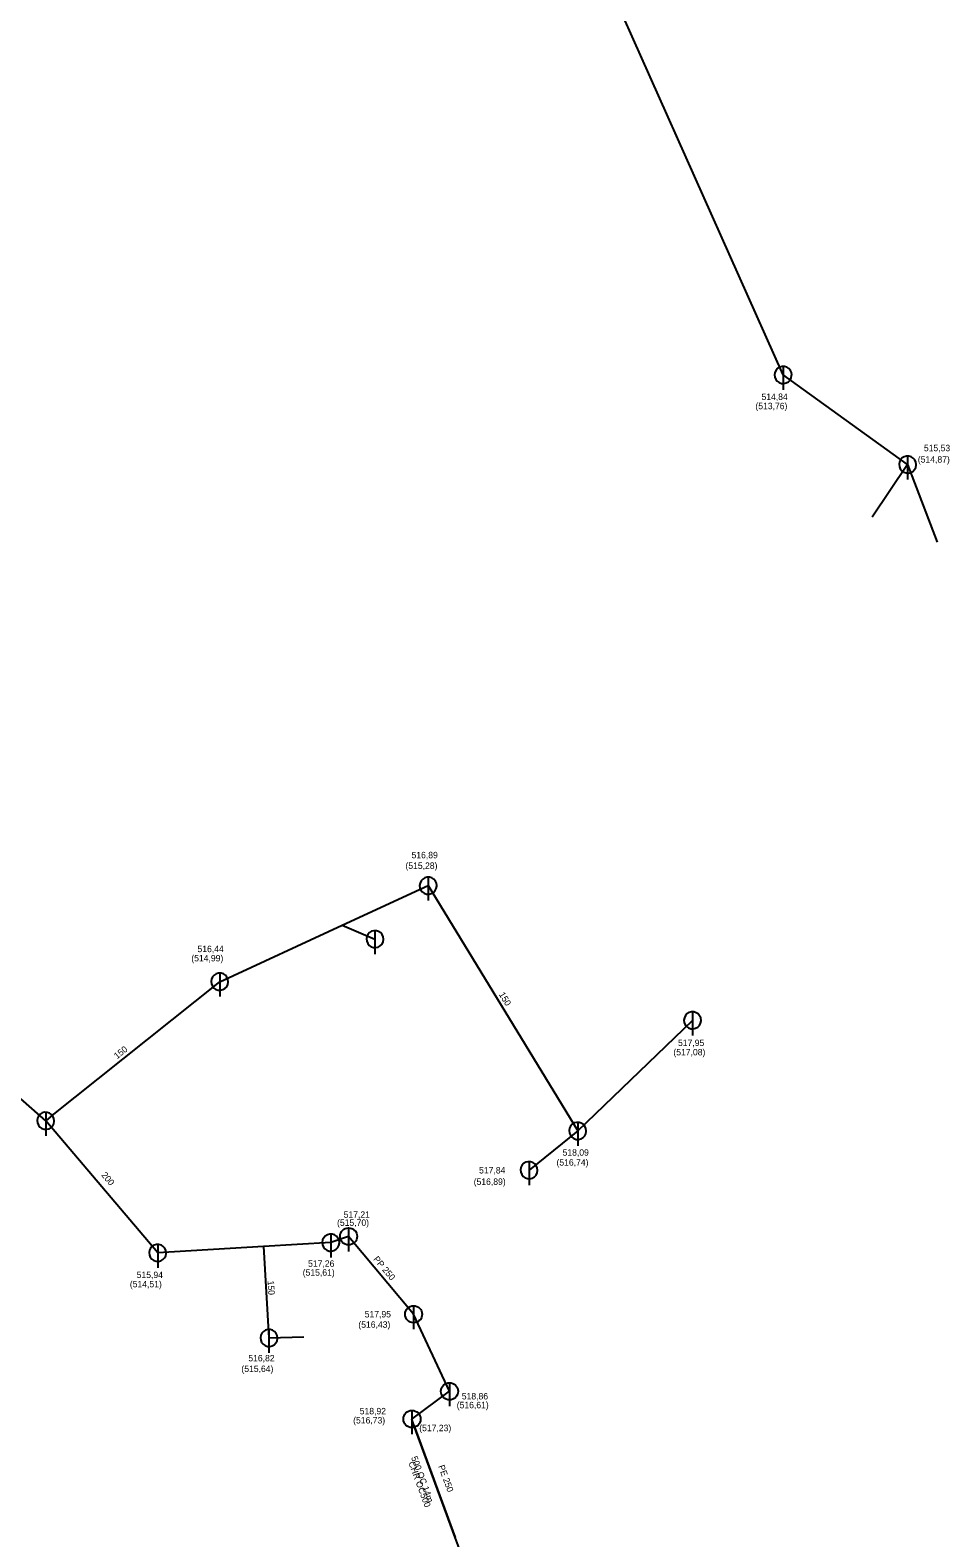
# Model space of a CAD drawing. Extents: x -476058 to -471893, y -1155786 to -1152000.
# Drawn here: x -474946.6 to -474839.2, y -1154439.5 to -1154263.3 of the extents above; entities that cross this region are included whole.
import ezdxf

# ---------------------------------------------------------------- set-up
doc = ezdxf.new("R2010")
doc.units = 0
for name, color, linetype in [('Vrstva 10', 7, 'Continuous'), ('Vrstva 17', 7, 'Continuous'), ('Vrstva 18', 7, 'Continuous'), ('Vrstva 19', 7, 'Continuous'), ('Vrstva 20', 7, 'Continuous'), ('Vrstva 23', 7, 'Continuous'), ('Vrstva 3', 7, 'Continuous'), ('Vrstva 4', 7, 'Continuous'), ('Vrstva 40', 7, 'Continuous'), ('Vrstva 45', 7, 'Continuous'), ('Vrstva 50', 7, 'Continuous'), ('Vrstva 51', 7, 'Continuous')]:
    doc.layers.add(name, color=color, linetype=linetype)

msp = doc.modelspace()

# ---------------------------------------------------------------- linework, layer by layer
at = {"layer": 'Vrstva 10'}
for p, q in [((-474858.62, -1154302.63), (-474858.62, -1154305.38)), ((-474844.08, -1154313.1), (-474844.08, -1154315.85)), ((-474900.08, -1154362.3), (-474900.08, -1154365.05)), ((-474906.29, -1154368.55), (-474906.29, -1154371.3)), ((-474924.42, -1154373.52), (-474924.42, -1154376.27)), ((-474869.21, -1154378.04), (-474869.21, -1154380.79)), ((-474944.74, -1154389.78), (-474944.74, -1154392.52)), ((-474882.61, -1154390.95), (-474882.61, -1154393.7)), ((-474888.29, -1154395.54), (-474888.29, -1154398.29)), ((-474911.45, -1154404.01), (-474911.45, -1154406.75)), ((-474909.37, -1154403.28), (-474909.37, -1154406.03)), ((-474931.67, -1154405.2), (-474931.67, -1154407.95)), ((-474901.78, -1154412.38), (-474901.78, -1154415.13)), ((-474918.67, -1154415.15), (-474918.67, -1154417.9)), ((-474897.59, -1154421.38), (-474897.59, -1154424.13)), ((-474901.97, -1154424.62), (-474901.97, -1154427.37))]:
    msp.add_line(p, q, dxfattribs=at)
for points in [[(-474857.62, -1154303.63), (-474857.66, -1154303.35), (-474857.78, -1154303.1), (-474857.96, -1154302.88), (-474858.2, -1154302.73), (-474858.47, -1154302.65), (-474858.75, -1154302.64), (-474859.02, -1154302.72), (-474859.26, -1154302.86), (-474859.45, -1154303.07), (-474859.58, -1154303.33), (-474859.62, -1154303.61), (-474859.59, -1154303.89), (-474859.48, -1154304.15), (-474859.31, -1154304.37), (-474859.08, -1154304.53), (-474858.81, -1154304.62), (-474858.53, -1154304.63), (-474858.25, -1154304.56), (-474858.01, -1154304.42), (-474857.81, -1154304.22), (-474857.68, -1154303.97), (-474857.63, -1154303.69), (-474857.62, -1154303.63)], [(-474843.08, -1154314.1), (-474843.12, -1154313.82), (-474843.24, -1154313.56), (-474843.42, -1154313.35), (-474843.66, -1154313.19), (-474843.93, -1154313.11), (-474844.21, -1154313.11), (-474844.48, -1154313.18), (-474844.72, -1154313.33), (-474844.91, -1154313.54), (-474845.03, -1154313.79), (-474845.08, -1154314.07), (-474845.05, -1154314.35), (-474844.94, -1154314.61), (-474844.76, -1154314.83), (-474844.53, -1154314.99), (-474844.26, -1154315.08), (-474843.98, -1154315.09), (-474843.71, -1154315.03), (-474843.46, -1154314.89), (-474843.27, -1154314.68), (-474843.14, -1154314.43), (-474843.08, -1154314.16), (-474843.08, -1154314.1)], [(-474899.08, -1154363.3), (-474899.12, -1154363.02), (-474899.24, -1154362.76), (-474899.42, -1154362.55), (-474899.66, -1154362.4), (-474899.93, -1154362.31), (-474900.21, -1154362.31), (-474900.48, -1154362.38), (-474900.72, -1154362.53), (-474900.91, -1154362.74), (-474901.03, -1154362.99), (-474901.08, -1154363.27), (-474901.05, -1154363.55), (-474900.94, -1154363.81), (-474900.76, -1154364.03), (-474900.53, -1154364.19), (-474900.26, -1154364.28), (-474899.98, -1154364.3), (-474899.71, -1154364.23), (-474899.46, -1154364.09), (-474899.27, -1154363.88), (-474899.14, -1154363.63), (-474899.08, -1154363.36), (-474899.08, -1154363.3)], [(-474905.29, -1154369.55), (-474905.32, -1154369.27), (-474905.44, -1154369.01), (-474905.62, -1154368.8), (-474905.86, -1154368.64), (-474906.13, -1154368.56), (-474906.41, -1154368.56), (-474906.68, -1154368.63), (-474906.92, -1154368.78), (-474907.11, -1154368.99), (-474907.24, -1154369.24), (-474907.29, -1154369.52), (-474907.25, -1154369.8), (-474907.14, -1154370.06), (-474906.97, -1154370.28), (-474906.73, -1154370.44), (-474906.47, -1154370.53), (-474906.18, -1154370.54), (-474905.91, -1154370.48), (-474905.67, -1154370.34), (-474905.47, -1154370.13), (-474905.34, -1154369.88), (-474905.29, -1154369.6), (-474905.29, -1154369.55)], [(-474923.42, -1154374.52), (-474923.46, -1154374.25), (-474923.58, -1154373.99), (-474923.76, -1154373.77), (-474924, -1154373.62), (-474924.27, -1154373.54), (-474924.55, -1154373.53), (-474924.82, -1154373.61), (-474925.06, -1154373.76), (-474925.25, -1154373.96), (-474925.38, -1154374.22), (-474925.42, -1154374.5), (-474925.39, -1154374.78), (-474925.28, -1154375.04), (-474925.11, -1154375.26), (-474924.88, -1154375.42), (-474924.61, -1154375.51), (-474924.33, -1154375.52), (-474924.05, -1154375.45), (-474923.81, -1154375.31), (-474923.61, -1154375.11), (-474923.48, -1154374.86), (-474923.43, -1154374.58), (-474923.42, -1154374.52)], [(-474868.21, -1154379.04), (-474868.25, -1154378.76), (-474868.37, -1154378.5), (-474868.55, -1154378.29), (-474868.79, -1154378.14), (-474869.05, -1154378.05), (-474869.34, -1154378.05), (-474869.61, -1154378.12), (-474869.85, -1154378.27), (-474870.04, -1154378.48), (-474870.16, -1154378.73), (-474870.21, -1154379.01), (-474870.18, -1154379.29), (-474870.07, -1154379.55), (-474869.89, -1154379.77), (-474869.66, -1154379.93), (-474869.39, -1154380.02), (-474869.11, -1154380.04), (-474868.84, -1154379.97), (-474868.59, -1154379.83), (-474868.4, -1154379.62), (-474868.27, -1154379.37), (-474868.21, -1154379.1), (-474868.21, -1154379.04)], [(-474943.74, -1154390.78), (-474943.78, -1154390.5), (-474943.9, -1154390.24), (-474944.08, -1154390.02), (-474944.32, -1154389.87), (-474944.59, -1154389.79), (-474944.87, -1154389.78), (-474945.14, -1154389.86), (-474945.38, -1154390.01), (-474945.57, -1154390.22), (-474945.69, -1154390.47), (-474945.74, -1154390.75), (-474945.71, -1154391.03), (-474945.6, -1154391.29), (-474945.42, -1154391.51), (-474945.19, -1154391.67), (-474944.92, -1154391.76), (-474944.64, -1154391.77), (-474944.37, -1154391.7), (-474944.12, -1154391.56), (-474943.93, -1154391.36), (-474943.8, -1154391.11), (-474943.74, -1154390.83), (-474943.74, -1154390.78)], [(-474881.61, -1154391.95), (-474881.65, -1154391.67), (-474881.77, -1154391.42), (-474881.95, -1154391.2), (-474882.19, -1154391.05), (-474882.46, -1154390.96), (-474882.74, -1154390.96), (-474883.01, -1154391.03), (-474883.25, -1154391.18), (-474883.44, -1154391.39), (-474883.57, -1154391.65), (-474883.61, -1154391.92), (-474883.58, -1154392.21), (-474883.47, -1154392.47), (-474883.29, -1154392.68), (-474883.06, -1154392.85), (-474882.79, -1154392.94), (-474882.51, -1154392.95), (-474882.24, -1154392.88), (-474881.99, -1154392.74), (-474881.8, -1154392.53), (-474881.67, -1154392.28), (-474881.61, -1154392.01), (-474881.61, -1154391.95)], [(-474887.29, -1154396.54), (-474887.33, -1154396.26), (-474887.45, -1154396.01), (-474887.63, -1154395.79), (-474887.86, -1154395.64), (-474888.14, -1154395.55), (-474888.42, -1154395.55), (-474888.69, -1154395.62), (-474888.93, -1154395.77), (-474889.12, -1154395.98), (-474889.24, -1154396.24), (-474889.29, -1154396.51), (-474889.26, -1154396.79), (-474889.15, -1154397.05), (-474888.97, -1154397.27), (-474888.74, -1154397.44), (-474888.47, -1154397.53), (-474888.19, -1154397.54), (-474887.92, -1154397.47), (-474887.67, -1154397.33), (-474887.48, -1154397.12), (-474887.35, -1154396.87), (-474887.29, -1154396.6), (-474887.29, -1154396.54)], [(-474910.45, -1154405.01), (-474910.49, -1154404.73), (-474910.61, -1154404.47), (-474910.79, -1154404.25), (-474911.03, -1154404.1), (-474911.3, -1154404.02), (-474911.58, -1154404.01), (-474911.85, -1154404.09), (-474912.09, -1154404.24), (-474912.28, -1154404.45), (-474912.4, -1154404.7), (-474912.45, -1154404.98), (-474912.42, -1154405.26), (-474912.31, -1154405.52), (-474912.13, -1154405.74), (-474911.9, -1154405.9), (-474911.63, -1154405.99), (-474911.35, -1154406), (-474911.08, -1154405.93), (-474910.83, -1154405.79), (-474910.64, -1154405.59), (-474910.51, -1154405.34), (-474910.45, -1154405.06), (-474910.45, -1154405.01)], [(-474930.67, -1154406.2), (-474930.71, -1154405.93), (-474930.83, -1154405.67), (-474931.01, -1154405.45), (-474931.24, -1154405.3), (-474931.52, -1154405.22), (-474931.8, -1154405.21), (-474932.07, -1154405.29), (-474932.31, -1154405.44), (-474932.5, -1154405.64), (-474932.62, -1154405.9), (-474932.67, -1154406.18), (-474932.64, -1154406.46), (-474932.53, -1154406.72), (-474932.35, -1154406.94), (-474932.12, -1154407.1), (-474931.85, -1154407.19), (-474931.57, -1154407.2), (-474931.3, -1154407.13), (-474931.05, -1154406.99), (-474930.86, -1154406.79), (-474930.73, -1154406.54), (-474930.67, -1154406.26), (-474930.67, -1154406.2)], [(-474917.67, -1154416.15), (-474917.71, -1154415.87), (-474917.83, -1154415.61), (-474918.01, -1154415.4), (-474918.25, -1154415.24), (-474918.52, -1154415.16), (-474918.8, -1154415.16), (-474919.07, -1154415.23), (-474919.31, -1154415.38), (-474919.5, -1154415.59), (-474919.63, -1154415.84), (-474919.67, -1154416.12), (-474919.64, -1154416.4), (-474919.53, -1154416.66), (-474919.36, -1154416.88), (-474919.12, -1154417.04), (-474918.86, -1154417.13), (-474918.58, -1154417.15), (-474918.3, -1154417.08), (-474918.06, -1154416.94), (-474917.86, -1154416.73), (-474917.73, -1154416.48), (-474917.68, -1154416.21), (-474917.67, -1154416.15)]]:
    msp.add_lwpolyline(points, dxfattribs=at)
for centre in [(-474909.37, -1154404.28), (-474901.78, -1154413.38), (-474897.59, -1154422.38), (-474901.97, -1154425.62)]:
    msp.add_circle(centre, 1, dxfattribs=at)
at = {"layer": 'Vrstva 23'}
msp.add_lwpolyline([(-474901.74, -1154426.35), (-474896.91, -1154439.45)], dxfattribs=at)
at = {"layer": 'Vrstva 40'}
for points in [[(-474909.37, -1154404.28), (-474911.45, -1154405.01)], [(-474901.78, -1154413.38), (-474909.37, -1154404.28)], [(-474897.59, -1154422.38), (-474901.78, -1154413.38)], [(-474901.97, -1154425.62), (-474897.59, -1154422.38)], [(-474901.74, -1154426.35), (-474901.97, -1154425.62)], [(-474896.91, -1154439.45), (-474901.74, -1154426.35)], [(-474895.29, -1154443.83), (-474896.91, -1154439.45)]]:
    msp.add_lwpolyline(points, dxfattribs=at)
at = {"layer": 'Vrstva 45'}
for points in [[(-474944.74, -1154390.78), (-474991.72, -1154349.41)], [(-474931.67, -1154406.2), (-474944.74, -1154390.78)], [(-474919.31, -1154405.47), (-474931.67, -1154406.2)], [(-474911.45, -1154405.01), (-474919.31, -1154405.47)]]:
    msp.add_lwpolyline(points, dxfattribs=at)
at = {"layer": 'Vrstva 50'}
msp.add_line((-474919.31, -1154405.47), (-474918.67, -1154416.15), dxfattribs=at)
for points in [[(-474858.62, -1154303.63), (-474879.33, -1154257.17)], [(-474844.08, -1154314.1), (-474858.62, -1154303.63)], [(-474910.12, -1154367.93), (-474900.08, -1154363.3)], [(-474900.08, -1154363.3), (-474882.61, -1154391.95)], [(-474924.42, -1154374.52), (-474910.12, -1154367.93)], [(-474944.17, -1154390.32), (-474924.42, -1154374.52)], [(-474882.61, -1154391.95), (-474869.21, -1154379.04)], [(-474944.17, -1154390.32), (-474944.74, -1154390.78)], [(-474882.61, -1154391.95), (-474888.29, -1154396.54)]]:
    msp.add_lwpolyline(points, dxfattribs=at)
at = {"layer": 'Vrstva 51'}
for points in [[(-474844.08, -1154314.1), (-474848.21, -1154320.25)], [(-474844.08, -1154314.1), (-474840.65, -1154323.17)], [(-474910.12, -1154367.93), (-474906.29, -1154369.55)], [(-474918.67, -1154416.15), (-474914.59, -1154416.03)]]:
    msp.add_lwpolyline(points, dxfattribs=at)

# ---------------------------------------------------------------- texts
at = {"layer": 'Vrstva 17'}
for s, rotation, p in [('PP 250', 309.795, (-474906.53, -1154406.97)), ('PE 250', 290.1161, (-474898.92, -1154431.14))]:
    msp.add_text(s, height=0.75, rotation=rotation, dxfattribs=at).set_placement(p)
at = {"layer": 'Vrstva 18'}
msp.add_text('200 ', height=0.75, rotation=310.2725, dxfattribs=at).set_placement((-474938.3, -1154397.15))
at = {"layer": 'Vrstva 19'}
for rotation, p in [(301.369, (-474891.85, -1154376.01)), (38.6556, (-474936.41, -1154383.6)), (273.3926, (-474918.83, -1154409.47))]:
    msp.add_text('150 ', height=0.75, rotation=rotation, dxfattribs=at).set_placement(p)
at = {"layer": 'Vrstva 20'}
for s, p in [('CHR OC500', (-474902.4, -1154430.73)), (' 500 OC 14m', (-474902.18, -1154429.86))]:
    msp.add_text(s, height=0.75, rotation=290.2717, dxfattribs=at).set_placement(p)
at = {"layer": 'Vrstva 3'}
for s, p in [('514,84', (-474861.15, -1154306.55)), ('515,53', (-474842.18, -1154312.54)), ('516,89', (-474902.02, -1154360.1)), ('516,44', (-474927.02, -1154371.07)), ('517,95', (-474870.9, -1154382.04)), ('518,09', (-474884.38, -1154394.85)), ('517,84', (-474894.13, -1154396.93)), ('517,21', (-474909.95, -1154402.11)), ('517,26', (-474914.1, -1154407.83)), ('515,94', (-474934.12, -1154409.15)), ('517,95', (-474907.49, -1154413.75)), ('516,82', (-474921.08, -1154418.88)), ('518,86', (-474896.15, -1154423.33)), ('518,92', (-474908.07, -1154425.07))]:
    msp.add_text(s, height=0.75, dxfattribs=at).set_placement(p)
at = {"layer": 'Vrstva 4'}
for s, p in [('(513,76)', (-474861.86, -1154307.63)), ('(514,87)', (-474842.89, -1154313.87)), ('(515,28)', (-474902.73, -1154361.34)), ('(514,99)', (-474927.74, -1154372.15)), ('(517,08)', (-474871.44, -1154383.13)), ('(516,74)', (-474885.09, -1154396.01)), ('(516,89)', (-474894.76, -1154398.26)), ('(515,70)', (-474910.72, -1154403.05)), ('(515,61)', (-474914.73, -1154408.87)), ('(514,51)', (-474934.92, -1154410.23)), ('(516,43)', (-474908.23, -1154414.96)), ('(515,64)', (-474921.89, -1154420.12)), ('(516,61)', (-474896.74, -1154424.36)), ('(516,73)', (-474908.84, -1154426.14)), ('(517,23)', (-474901.12, -1154427.04))]:
    msp.add_text(s, height=0.75, dxfattribs=at).set_placement(p)

doc.saveas('drawing.dxf')
